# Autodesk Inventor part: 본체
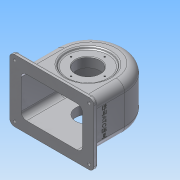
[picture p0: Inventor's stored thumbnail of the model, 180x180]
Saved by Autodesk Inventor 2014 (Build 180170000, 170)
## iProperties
Created: 2016-01
Part Number: 본체
Material: 알루미늄 6061
Document SubType Name: Modeling
Designer: user
Mass: 809.57 g
Surface Area: 999.651 cm^2
Volume: 298.734 cm^3
Density: 2.71 g/cm^3
Appearance: 알루미늄 - 평지
Author: user
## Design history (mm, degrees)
sketch "스케치1"
  geometry: L1 (-57, 0)-(-57, -64); L2 (-57, -64)-(57, -64); L3 (57, -64)-(57, 0); A1 r 57 centre (0, 0) between (57, 0) and (-57, 0); 1 further point
  constraints: 6 end point, 2 horizontal alignment, 2 point on circle, 2 vertical, 1 centre point, 1 coincident, 1 perpendicular
  dimensions: "d0" = 64 distance of L2.end L3.end; "d1" = 57 radius of A1
extrude "돌출1" new body sketch "스케치1" stored distance "d2" = 77; taper "d3" = 0 deg
sketch "스케치2"
  geometry: L1 (57, 0)-(57, -64) reference; L2 (57, -64)-(-57, -64) reference; L3 (-57, -64)-(-57, 0) reference; L4 (-51, -64)-(-51, 0); L5 (51, 0)-(51, -64); A1 r 57 centre (0, 0) between (57, 0) and (-57, 0) reference; A2 r 51 centre (0, 0) between (51, 0) and (-51, 0); 1 further point
  constraints: 4 end point, 2 point on circle, 2 point on line, 2 tangent, 1 centre point, 1 parallel, 1 perpendicular
  dimensions: "d4" = 6 distance between parallel lines of L1 L5; "d5" = 6 distance between parallel lines of L3 L4; "d6" = 6 radial gap between concentric circles of A1 A2
extrude "돌출2" cut sketch "스케치2" stored distance "d7" = 67; taper "d8" = 0 deg
sketch "스케치3"
  geometry: L1 (114, -77)-(114, 0) reference; L2 (0, 0)-(114, 0) reference; L3 (0, -77)-(0, 0) reference; L4 (114, -77)-(0, -77) reference; L5 (-13, -90.5)-(127, -90.5); L6 (127, -90.5)-(127, 13.5); L7 (127, 13.5)-(-13, 13.5); L8 (-13, 13.5)-(-13, -90.5); L9 (-13, -90.5)-(127, 13.5); L10 (127, -90.5)-(-13, 13.5); 1 further point
  constraints: 12 end point, 2 midpoint, 2 parallel, 1 horizontal, 1 perpendicular
  dimensions: "d9" = 140 distance of L6.end L7.end; "d10" = 104 distance of L5.end L6.end
extrude "돌출3" join sketch "스케치3" distance "d11" = 7; taper "d12" = 0 deg
sketch "스케치4"
  geometry: L1 (51, 33.5)-(0, 33.5) reference; L2 (0, 33.5)-(-64, 33.5) reference; L3 (35.747, 33.5)-(24, 19.5); L4 (24, 19.5)-(-4, 19.5); L5 (-4, 33.5)-(-4, 19.5); L6 (-64, 52)-(-64, -52) reference; L7 (57, 38.5)-(0, 38.5) reference; 1 further point
  constraints: 6 end point, 2 point on line, 1 parallel, 1 vertical
  dimensions: "d13" = 60 distance between parallel lines of L6 L5; "d14" = 56 diameter of L3.end L5; "d15" = 19 distance between parallel lines of L4 L7; "d16" = 50 deg angle of L4 L3
revolve "회전1" sketch "스케치4" stored, may be unused: angle "d17" = 90 deg
sketch "스케치5"
  geometry: L1 (57, 38.5)-(0, 38.5) reference; L2 (-32, 19.5)-(24, 19.5) reference; L3 (-4, 19.5)-(-4, 38.5); L4 (35.747, 33.5)-(24, 19.5) reference; L5 (33.416, 38.5)-(30.899, 35.5); L6 (-4, 38.5)-(33.416, 38.5); L7 (30.899, 35.5)-(-4, 35.5); 1 further point
  constraints: 8 end point, 2 perpendicular, 2 point on line, 1 horizontal alignment, 1 midpoint, 1 parallel
  dimensions: "d19" = 5 distance between parallel lines of L4 L5; "d20" = 3 vertical distance of L5.start L5.end
revolve "회전2" sketch "스케치5" stored, may be unused: angle "d21" = 90 deg
sketch "스케치6"
  geometry: L1 (0, -38.5)-(57, -38.5) reference; L2 (-4, -38.5)-(27, -38.5); L3 (27, -38.5)-(27, -48.5); L4 (27, -48.5)-(-4, -48.5); L5 (-4, -48.5)-(-4, -38.5); L6 (-64, 52)-(-64, -52) reference; 1 further point
  constraints: 8 end point, 2 parallel, 1 horizontal, 1 perpendicular, 1 point on line
  dimensions: "d22" = 60 distance between parallel lines of L5 L6; "d23" = 10 distance of L2.end L3.end; "d24" = 62 diameter of L3 L5
revolve "회전3" sketch "스케치6" stored, may be unused: angle "d25" = 90 deg
node "작업 평면2"
  node "작업 평면1"
sketch "스케치7"
  geometry: C1 r 6 at (0, 0); 1 further point
  constraints: 1 centre point, 1 coincident
  dimensions: "d27" = 12 diameter of C1
extrude "돌출4" join sketch "스케치7" stored distance "d28" = 7; taper "d29" = 0 deg
fillet "모깎기1" dims "d30" = 3
fillet "모깎기2" dims "d31" = 9
fillet "모깎기3" dims "d32" = 14
fillet "모깎기4" dims "d33" = 1
fillet "모깎기5" dims "d34" = 8
fillet "모깎기6" dims "d35" = 3
fillet "모깎기7" dims "d36" = 3
hole "구멍1" diameter "d39" = 40; stored, may be unused: countersink angle "d43" = 90 deg, drill point angle "d45" = 0 deg; dims "d37" = 10, "d38" = 10, "d40" = 6, "d41" = 4, "d42" = 2, "d44" = 20
hole "구멍2" diameter "d48" = 40; stored, may be unused: countersink angle "d52" = 90 deg, drill point angle "d54" = 0 deg; dims "d46" = 10, "d47" = 10, "d49" = 6, "d50" = 4, "d51" = 2, "d53" = 20
chamfer "모따기1" distance "d55" = 1; stored, may be unused: second distance "d56" = 2, angle "d57" = 45 deg
fillet "모깎기8" dims "d58" = 3
sketch "스케치8"
  geometry: C1 r 21 at (0, 0) reference; 2 further points
  constraints: 1 vertical alignment
  dimensions: "d59" = 28 distance of C1.centre point (0, 28)
hole "구멍3" sketch "스케치8" at (0, 28) diameter "d60" = 2.459; stored, may be unused: countersink angle "d64" = 90 deg, drill point angle "d66" = 118 deg; dims "d61" = 7, "d62" = 4, "d63" = 2, "d65" = 9
sketch "스케치9"
  geometry: C1 r 31 at (0, 0) reference; 2 further points
  constraints: 1 vertical alignment
  dimensions: "d70" = 24 distance of C1.centre point (0, 24)
hole "구멍4" sketch "스케치9" at (0, 24) diameter "d71" = 2.459; stored, may be unused: countersink angle "d75" = 90 deg, drill point angle "d77" = 118 deg; dims "d72" = 6, "d73" = 4, "d74" = 2, "d76" = 8
hole "구멍5" diameter "d83" = 4.459; stored, may be unused: countersink angle "d87" = 90 deg, drill point angle "d89" = 0 deg; dims "d84" = 20, "d85" = 4, "d86" = 2, "d88" = 8, "d90" = 10, "d91" = 10
hole "구멍6" diameter "d94" = 5; stored, may be unused: countersink angle "d98" = 90 deg, drill point angle "d100" = 0 deg; dims "d92" = 10, "d93" = 10, "d95" = 8, "d96" = 4, "d97" = 2, "d99" = 8
sketch "스케치10"
  geometry: L1 (-19.5, -64)-(-27.5, -64) reference; L2 (-14, 0)-(-14, -56) reference; 2 further points
  constraints: 1 other
  dimensions: "d107" = 30 distance from line of point (24.5, -34) L1; "d108" = 38.5 distance from line of point (24.5, -34) L2
feature "엠보싱1" sketch "스케치10" dims "d0" = 64, "d1" = 57, "d109" = 0.5, "d110" = 0
node "솔리드1"
pattern_circular "원형 패턴1" dims angle "d68" = 360 deg
pattern_circular "원형 패턴2" dims angle "d79" = 360 deg
pattern_linear "직사각형 패턴1" dims "d103" = 88, "d106" = 124
node "투영된 루프1"
other parameters: "d26" = 6
